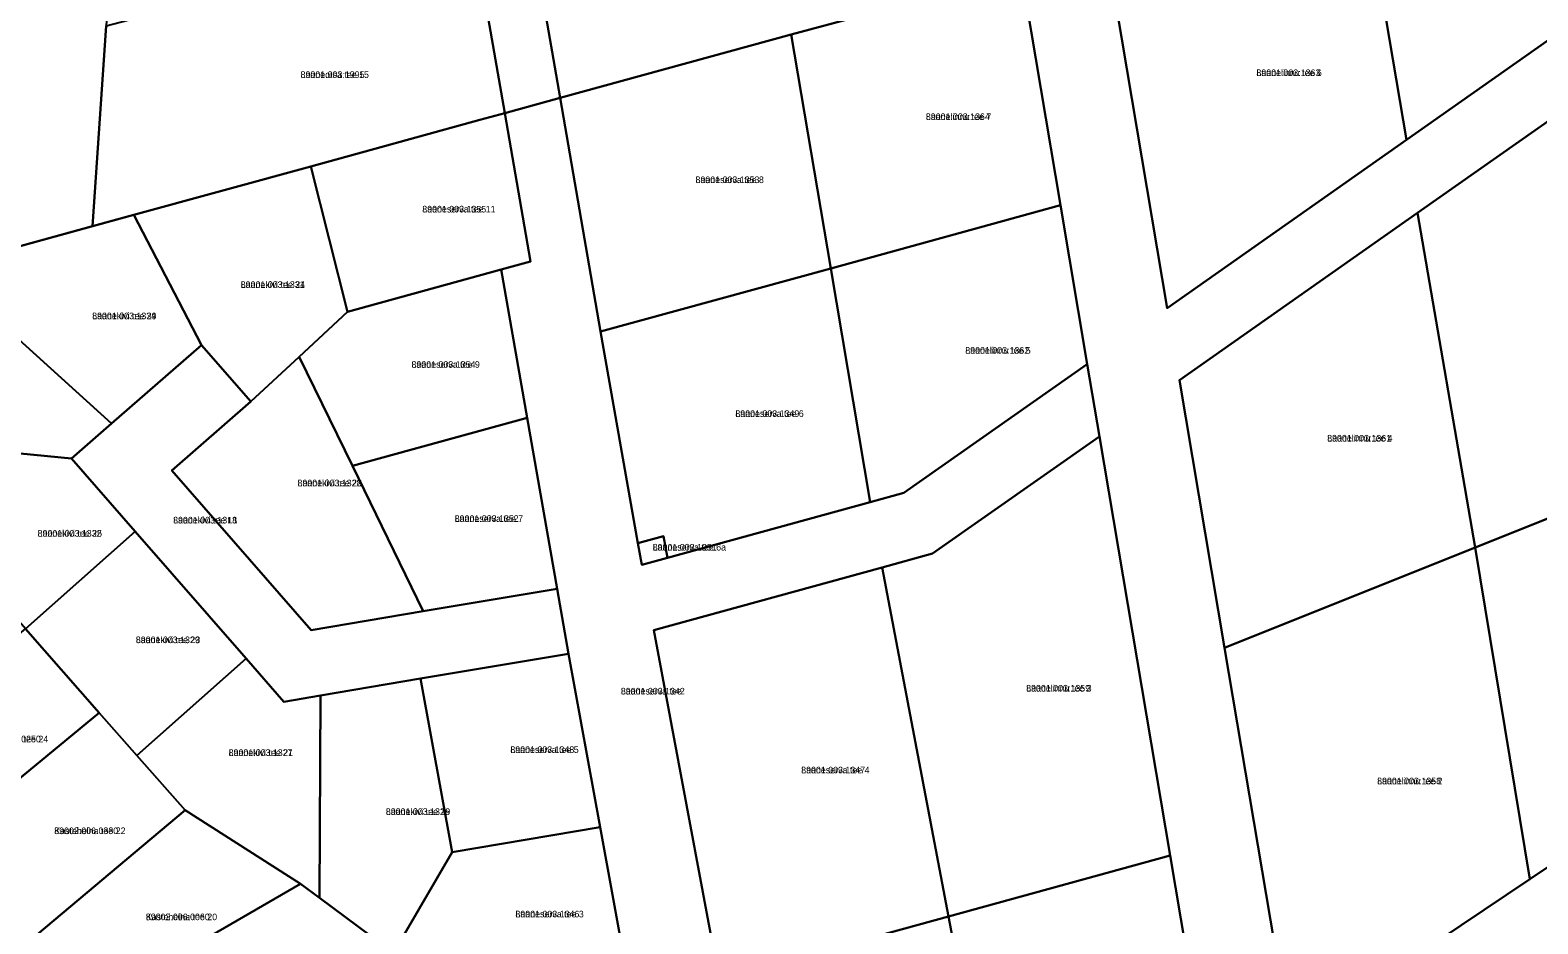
# Model space of a CAD drawing. Extents: x 526849 to 562296, y 6591741 to 6618546.
# Drawn here: x 545499.6 to 545841.5, y 6598774.9 to 6598977.5 of the extents above; entities that cross this region are included whole.
import ezdxf

# ---------------------------------------------------------------- set-up
doc = ezdxf.new("R2010")
doc.units = 0
for name, color, linetype in [('L_AADRESS', 7, 'Continuous'), ('PIIR', 7, 'Continuous'), ('TUNNUS', 7, 'Continuous')]:
    doc.layers.add(name, color=color, linetype=linetype)

msp = doc.modelspace()

# ---------------------------------------------------------------- linework, layer by layer
at = {"layer": 'PIIR'}
for points in [[(545521.49, 6599046.31), (545521.27, 6599043.15), (545516.81, 6598978.5), (545513.68, 6598933.1), (545479.11, 6598923.58), (545462.59, 6598919.09), (545464.44, 6598947.01), (545466.24, 6598974.19), (545468.44, 6599003.73), (545470.3, 6599032.68)], [(545801.65, 6599012.06), (545842.46, 6599023.25), (545863.67, 6599029.07), (545864.66, 6599023.38), (545865.68, 6599017.46), (545867.5, 6599006.94), (545863.73, 6598999.35), (545856.02, 6598983.78), (545811.67, 6598952.62)], [(545678.06, 6599027.5), (545686.02, 6598980.25), (545672.18, 6598976.54), (545619.79, 6598962.17), (545611.45, 6599010.04)], [(545743.66, 6598996.15), (545801.65, 6599012.06), (545811.67, 6598952.62), (545757.42, 6598914.51)], [(545599.95, 6599000.28), (545607.2, 6598958.71), (545601.56, 6598957.17), (545563.22, 6598946.64), (545523.1, 6598935.65), (545513.68, 6598933.1), (545516.81, 6598978.5), (545594.92, 6598998.97)], [(545724.28, 6598990.83), (545743.66, 6598996.15), (545757.42, 6598914.51), (545811.67, 6598952.62), (545856.02, 6598983.78), (545863.73, 6598999.35), (545868.19, 6598974), (545814.2, 6598936.07), (545760.19, 6598898.12), (545770.41, 6598837.49), (545784.6, 6598753.32), (545798.04, 6598757.01), (545839.67, 6598784.98), (545894.9, 6598822.08), (545898.86, 6598799.59), (545899.38, 6598796.63), (545865.04, 6598772.71), (545827.29, 6598748.35), (545779.42, 6598717.89), (545768.89, 6598726.19), (545758.08, 6598790.33), (545742.05, 6598885.38), (545739.29, 6598901.77), (545733.21, 6598937.82)], [(545672.18, 6598976.54), (545686.02, 6598980.25), (545724.28, 6598990.83), (545733.21, 6598937.82), (545681.13, 6598923.51)], [(545619.79, 6598962.17), (545672.18, 6598976.54), (545681.13, 6598923.51), (545628.92, 6598909.18)], [(545814.2, 6598936.07), (545868.19, 6598974), (545884.22, 6598882.93), (545827.24, 6598860.18)], [(545563.22, 6598946.64), (545601.56, 6598957.17), (545607.2, 6598958.71), (545613.08, 6598925.05), (545606.41, 6598923.22), (545571.56, 6598913.65)], [(545523.1, 6598935.65), (545563.22, 6598946.64), (545571.56, 6598913.65), (545560.57, 6598903.47), (545549.59, 6598893.28), (545538.41, 6598906.08)], [(545681.13, 6598923.51), (545733.21, 6598937.82), (545739.29, 6598901.77), (545697.74, 6598872.58), (545690.07, 6598870.47)], [(545760.19, 6598898.12), (545814.2, 6598936.07), (545827.24, 6598860.18), (545770.41, 6598837.49)], [(545479.11, 6598923.58), (545523.1, 6598935.65), (545538.41, 6598906.08), (545518.03, 6598888.29)], [(545462.59, 6598919.09), (545479.11, 6598923.58), (545518.03, 6598888.29), (545508.97, 6598880.37), (545475.53, 6598883.61), (545467.96, 6598877.07), (545460.48, 6598885.72), (545461.21, 6598896.54)], [(545560.57, 6598903.47), (545571.56, 6598913.65), (545606.41, 6598923.22), (545612.29, 6598889.58), (545572.66, 6598878.7)], [(545628.92, 6598909.18), (545681.13, 6598923.51), (545690.07, 6598870.47), (545644.1, 6598857.85), (545643.22, 6598862.79), (545637.42, 6598861.2)], [(545508.97, 6598880.37), (545518.03, 6598888.29), (545538.41, 6598906.08), (545549.59, 6598893.28), (545531.7, 6598877.66), (545563.29, 6598841.5), (545588.73, 6598845.77), (545619.06, 6598850.86), (545621.64, 6598836.13), (545588.11, 6598830.47), (545565.43, 6598826.64), (545557.12, 6598825.24), (545548.57, 6598835.04), (545523.43, 6598863.82)], [(545531.7, 6598877.66), (545549.59, 6598893.28), (545560.57, 6598903.47), (545572.66, 6598878.7), (545588.73, 6598845.77), (545563.29, 6598841.5)], [(545572.66, 6598878.7), (545612.29, 6598889.58), (545619.06, 6598850.86), (545588.73, 6598845.77)], [(545692.83, 6598855.68), (545704.23, 6598858.81), (545742.05, 6598885.38), (545758.08, 6598790.33), (545707.87, 6598776.54)], [(545467.96, 6598877.07), (545475.53, 6598883.61), (545508.97, 6598880.37), (545523.43, 6598863.82), (545498.5, 6598841.74)], [(545827.24, 6598860.18), (545884.22, 6598882.93), (545894.9, 6598822.08), (545839.67, 6598784.98)], [(545498.5, 6598841.74), (545523.43, 6598863.82), (545548.57, 6598835.04), (545523.76, 6598813.08), (545515.25, 6598822.72)], [(545637.42, 6598861.2), (545643.22, 6598862.79), (545644.1, 6598857.85), (545638.29, 6598856.25)], [(545770.41, 6598837.49), (545827.24, 6598860.18), (545839.67, 6598784.98), (545798.04, 6598757.01), (545784.6, 6598753.32)], [(545641, 6598841.44), (545692.83, 6598855.68), (545707.87, 6598776.54), (545655.81, 6598762.24)], [(545459.74, 6598809.2), (545498.5, 6598841.74), (545515.25, 6598822.72), (545475.89, 6598790.33)], [(545523.76, 6598813.08), (545548.57, 6598835.04), (545557.12, 6598825.24), (545565.43, 6598826.64), (545565.18, 6598780.76), (545560.87, 6598783.96), (545534.74, 6598800.68)], [(545588.11, 6598830.47), (545621.64, 6598836.13), (545628.83, 6598796.78), (545595.3, 6598791.12)], [(545565.43, 6598826.64), (545588.11, 6598830.47), (545595.3, 6598791.12), (545584.3, 6598772.27), (545579.92, 6598769.82), (545565.18, 6598780.76)], [(545475.89, 6598790.33), (545515.25, 6598822.72), (545523.76, 6598813.08), (545534.74, 6598800.68), (545495.52, 6598767.72)], [(545510.14, 6598750.72), (545495.52, 6598767.72), (545534.74, 6598800.68), (545560.87, 6598783.96), (545533.56, 6598768.17)], [(545584.3, 6598772.27), (545595.3, 6598791.12), (545628.83, 6598796.78), (545634.9, 6598763.6), (545596.34, 6598755.88)], [(545707.87, 6598776.54), (545758.08, 6598790.33), (545768.89, 6598726.19), (545722.92, 6598697.41)], [(545524.31, 6598734.62), (545510.14, 6598750.72), (545533.56, 6598768.17), (545560.87, 6598783.96), (545565.18, 6598780.76), (545579.92, 6598769.82), (545553.69, 6598752.88)], [(545655.81, 6598762.24), (545707.87, 6598776.54), (545722.92, 6598697.41), (545685.48, 6598673.96), (545668.73, 6598693.14)]]:
    msp.add_lwpolyline(points, close=True, dxfattribs=at)
for points in [[(545611.45, 6599010.04), (545619.79, 6598962.17), (545607.2, 6598958.71), (545599.95, 6599000.28)], [(545634.9, 6598763.6), (545628.83, 6598796.78), (545621.64, 6598836.13), (545619.06, 6598850.86), (545612.29, 6598889.58), (545606.41, 6598923.22), (545613.08, 6598925.05), (545607.2, 6598958.71), (545619.79, 6598962.17), (545628.92, 6598909.18), (545637.42, 6598861.2), (545638.29, 6598856.25), (545644.1, 6598857.85), (545690.07, 6598870.47), (545697.74, 6598872.58), (545739.29, 6598901.77), (545742.05, 6598885.38), (545704.23, 6598858.81), (545692.83, 6598855.68), (545641, 6598841.44), (545655.81, 6598762.24)]]:
    msp.add_lwpolyline(points, dxfattribs=at)

# ---------------------------------------------------------------- texts
at = {"layer": 'L_AADRESS'}
for s, p in [('Laaneotsa tee 15', (545560.9, 6598966.69)), ('Laanelinnu tee 6', (545777.66, 6598967.11)), ('Laanelinnu tee 7', (545702.7, 6598957.15)), ('Laaneserva tee 8', (545650.46, 6598942.84)), ('Laaneserva tee 11', (545588.5, 6598936.18)), ('Laanekivi tee 24', (545547.33, 6598919.08)), ('Laanekivi tee 29', (545513.64, 6598911.97)), ('Laanelinnu tee 5', (545711.64, 6598904.15)), ('Laaneserva tee 9', (545586.05, 6598900.96)), ('Laaneserva tee 6', (545659.5, 6598889.82)), ('Laanelinnu tee 4', (545793.71, 6598884.24)), ('Laanekivi tee 22', (545560.21, 6598874.08)), ('Laaneserva tee 7', (545595.86, 6598866.02)), ('Laanekivi tee 25', (545501.27, 6598862.67)), ('Laanekivi tee L1', (545532, 6598865.66)), ('Laaneserva tee 6a', (545640.76, 6598859.52)), ('Laanekivi tee 23', (545523.54, 6598838.52)), ('Laaneserva tee', (545633.53, 6598826.88)), ('Laanelinnu tee 3', (545725.45, 6598827.55)), ('Kasteheina tee 24', (545487.5, 6598816.03)), ('Laanekivi tee 21', (545544.59, 6598812.95)), ('Laaneserva tee 5', (545608.47, 6598813.62)), ('Laaneserva tee 4', (545674.43, 6598808.99)), ('Laanelinnu tee 2', (545805.04, 6598806.51)), ('Laanekivi tee 19', (545580.24, 6598799.57)), ('Kasteheina tee 22', (545505.04, 6598795.22)), ('Kasteheina tee 20', (545525.8, 6598775.7)), ('Laaneserva tee 3', (545609.62, 6598776.33))]:
    msp.add_text(s, height=1.5, dxfattribs=at).set_placement(p)
at = {"layer": 'TUNNUS'}
for s, p in [('89001:003:1995', (545560.9, 6598966.69)), ('89001:003:1363', (545777.66, 6598967.11)), ('89001:003:1364', (545702.7, 6598957.15)), ('89001:003:1353', (545650.46, 6598942.84)), ('89001:003:1355', (545588.5, 6598936.18)), ('89001:003:1331', (545547.33, 6598919.08)), ('89001:003:1334', (545513.64, 6598911.97)), ('89001:003:1362', (545711.64, 6598904.15)), ('89001:003:1354', (545586.05, 6598900.96)), ('89001:003:1349', (545659.5, 6598889.82)), ('89001:003:1361', (545793.71, 6598884.24)), ('89001:003:1328', (545560.21, 6598874.08)), ('89001:003:1352', (545595.86, 6598866.02)), ('89001:003:1332', (545501.27, 6598862.67)), ('89001:003:1318', (545532, 6598865.66)), ('89001:003:1351', (545640.76, 6598859.52)), ('89001:003:1329', (545523.54, 6598838.52)), ('89001:003:1342', (545633.53, 6598826.88)), ('89001:003:1359', (545725.45, 6598827.55)), ('89002:006:0250', (545487.5, 6598816.03)), ('89001:003:1327', (545544.59, 6598812.95)), ('89001:003:1348', (545608.47, 6598813.62)), ('89001:003:1347', (545674.43, 6598808.99)), ('89001:003:1358', (545805.04, 6598806.51)), ('89001:003:1326', (545580.24, 6598799.57)), ('89002:006:0330', (545505.04, 6598795.22)), ('89002:006:0060', (545525.8, 6598775.7)), ('89001:003:1346', (545609.62, 6598776.33))]:
    msp.add_text(s, height=1.5, dxfattribs=at).set_placement(p)

doc.saveas('drawing.dxf')
